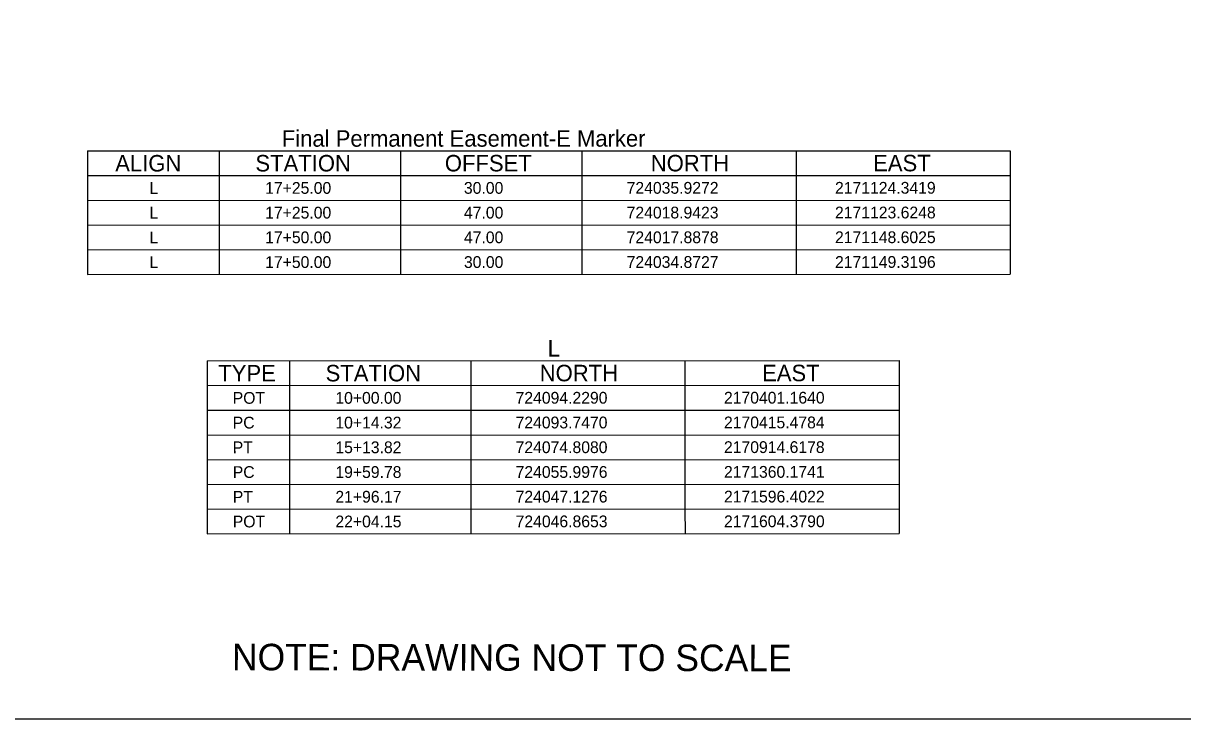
# Model space of a CAD drawing. Extents: x 2169223 to 2172151, y 723262 to 725175.
# Drawn here: x 2170358 to 2171309, y 723306 to 723876 of the extents above; entities that cross this region are included whole.
import ezdxf

# ---------------------------------------------------------------- set-up
doc = ezdxf.new("R2010")
doc.units = 0
for name, color, linetype in [('CTL Sheet Border CELL', 7, 'Continuous'), ('CTL Sheet Notes CELL', 7, 'Continuous'), ('CTL Sheet Table Cell', 7, 'Continuous'), ('CTL Sheet Text', 7, 'Continuous')]:
    doc.layers.add(name, color=color, linetype=linetype)

msp = doc.modelspace()

# ---------------------------------------------------------------- linework, layer by layer
at = {"layer": 'CTL Sheet Border CELL'}
msp.add_lwpolyline([(2172121.89, 725131.92), (2169513.19, 725131.84), (2169513.25, 723305.76), (2172121.95, 723305.85)], close=True, dxfattribs=at)
at = {"layer": 'CTL Sheet Table Cell'}
for p, q in [((2170410.96, 723771.1), (2171167.22, 723771.26)), ((2170410.96, 723771.1), (2170410.97, 723750.84)), ((2170519, 723771.12), (2170519, 723750.87)), ((2170667.55, 723771.16), (2170667.56, 723750.9)), ((2170816.1, 723771.19), (2170816.11, 723750.93)), ((2170991.66, 723771.23), (2170991.67, 723750.97)), ((2171167.22, 723771.26), (2171167.23, 723751.01)), ((2170410.97, 723750.84), (2171167.23, 723751.01)), ((2170410.97, 723750.84), (2170410.97, 723730.59)), ((2170519, 723750.87), (2170519.01, 723730.61)), ((2170667.56, 723750.9), (2170667.56, 723730.64)), ((2170816.11, 723750.93), (2170816.11, 723730.67)), ((2170991.67, 723750.97), (2170991.67, 723730.71)), ((2171167.23, 723751.01), (2171167.23, 723730.75)), ((2170410.97, 723730.59), (2171167.23, 723730.75)), ((2170410.97, 723730.59), (2170410.98, 723710.33)), ((2170519.01, 723730.61), (2170519.01, 723710.35)), ((2170667.56, 723730.64), (2170667.56, 723710.38)), ((2170816.11, 723730.67), (2170816.11, 723710.42)), ((2170991.67, 723730.71), (2170991.67, 723710.45)), ((2171167.23, 723730.75), (2171167.23, 723710.49)), ((2170410.98, 723710.33), (2171167.23, 723710.49)), ((2170410.98, 723710.33), (2170410.98, 723690.07)), ((2170519.01, 723710.35), (2170519.02, 723690.1)), ((2170667.56, 723710.38), (2170667.57, 723690.13)), ((2170816.11, 723710.42), (2170816.12, 723690.16)), ((2170991.67, 723710.45), (2170991.68, 723690.2)), ((2171167.23, 723710.49), (2171167.24, 723690.24)), ((2170410.98, 723690.07), (2171167.24, 723690.24)), ((2170410.98, 723690.07), (2170410.99, 723669.81)), ((2170519.02, 723690.1), (2170519.02, 723669.84)), ((2170667.57, 723690.13), (2170667.57, 723669.87)), ((2170816.12, 723690.16), (2170816.12, 723669.9)), ((2170991.68, 723690.2), (2170991.68, 723669.94)), ((2171167.24, 723690.24), (2171167.24, 723669.98)), ((2170410.99, 723669.81), (2171167.24, 723669.98)), ((2170509, 723599.07), (2171076.19, 723599.29)), ((2170509, 723599.07), (2170509.01, 723578.82)), ((2170576.52, 723599.1), (2170576.53, 723578.84)), ((2170725.07, 723599.16), (2170725.08, 723578.9)), ((2170900.63, 723599.23), (2170900.64, 723578.97)), ((2171076.19, 723599.29), (2171076.2, 723579.04)), ((2170509.01, 723578.82), (2171076.2, 723579.04)), ((2170509.01, 723578.82), (2170509.02, 723558.56)), ((2170576.53, 723578.84), (2170576.54, 723558.59)), ((2170725.08, 723578.9), (2170725.09, 723558.64)), ((2170900.64, 723578.97), (2170900.65, 723558.71)), ((2171076.2, 723579.04), (2171076.21, 723558.78)), ((2170509.02, 723558.56), (2171076.21, 723558.78)), ((2170509.02, 723558.56), (2170509.02, 723538.3)), ((2170576.54, 723558.59), (2170576.55, 723538.33)), ((2170725.09, 723558.64), (2170725.1, 723538.39)), ((2170900.65, 723558.71), (2170900.66, 723538.45)), ((2171076.21, 723558.78), (2171076.22, 723538.52)), ((2170509.02, 723538.3), (2171076.22, 723538.52)), ((2170509.02, 723538.3), (2170509.03, 723518.05)), ((2170576.55, 723538.33), (2170576.55, 723518.07)), ((2170725.1, 723538.39), (2170725.11, 723518.13)), ((2170900.66, 723538.45), (2170900.67, 723518.2)), ((2171076.22, 723538.52), (2171076.23, 723518.27)), ((2170509.03, 723518.05), (2171076.23, 723518.27)), ((2170509.03, 723518.05), (2170509.04, 723497.79)), ((2170576.55, 723518.07), (2170576.56, 723497.81)), ((2170725.11, 723518.13), (2170725.11, 723497.87)), ((2170900.67, 723518.2), (2170900.67, 723497.94)), ((2171076.23, 723518.27), (2171076.23, 723498.01)), ((2170509.04, 723497.79), (2171076.23, 723498.01)), ((2170576.56, 723497.81), (2170576.57, 723477.56)), ((2170725.11, 723497.87), (2170725.12, 723477.62)), ((2170900.67, 723497.94), (2170900.68, 723477.68)), ((2171076.23, 723498.01), (2171076.24, 723477.75)), ((2170509.04, 723497.79), (2170509.05, 723477.53)), ((2170509.05, 723477.53), (2171076.24, 723477.75)), ((2170509.05, 723477.53), (2170509.06, 723457.27)), ((2170576.57, 723477.56), (2170576.58, 723457.3)), ((2170725.12, 723477.62), (2170725.13, 723457.36)), ((2170900.68, 723477.68), (2170900.69, 723457.43)), ((2171076.24, 723477.75), (2171076.25, 723457.5)), ((2170509.06, 723457.27), (2171076.25, 723457.5))]:
    msp.add_line(p, q, dxfattribs=at)

# ---------------------------------------------------------------- texts
at = {"layer": 'CTL Sheet Border CELL'}
msp.add_text('NOTE: DRAWING NOT TO SCALE', height=21.7391, rotation=359.8966, dxfattribs=at).set_placement((2170529.39, 723345.53))
at = {"layer": 'CTL Sheet Notes CELL'}
for s, height, rotation, p in [('Final Permanent Easement-E Marker ', 13.5046, 0.01241, (2170570.25, 723774.51)), ('ALIGN', 13.505, 0.01241, (2170433.72, 723754.22)), ('STATION', 13.505, 0.01241, (2170548.62, 723754.25)), ('OFFSET', 13.505, 0.01241, (2170703.87, 723754.28)), ('NORTH', 13.505, 0.01241, (2170872.62, 723754.32)), ('EAST', 13.505, 0.01241, (2171054.88, 723754.36)), ('L', 13.5, 0.0223, (2170788.13, 723602.56)), ('TYPE', 13.505, 0.0223, (2170518.2, 723582.2)), ('STATION', 13.505, 0.0223, (2170606.14, 723582.23)), ('NORTH', 13.505, 0.0223, (2170781.6, 723582.3)), ('EAST', 13.505, 0.0223, (2170963.86, 723582.37))]:
    msp.add_text(s, height=height, rotation=rotation, dxfattribs=at).set_placement(p)
at = {"layer": 'CTL Sheet Text'}
for s, height, rotation, p in [('L', 9.65, 0.01241, (2170461.8, 723735.9)), ('17+25.00', 9.646, 0.01241, (2170556.6, 723735.92)), ('30.00', 9.646, 0.01241, (2170719.5, 723735.96)), ('724035.9272', 9.6461, 0.01241, (2170852.85, 723735.99)), ('2171124.3419', 9.6461, 0.01241, (2171023.62, 723736.02)), ('L', 9.65, 0.01241, (2170461.8, 723715.65)), ('17+25.00', 9.646, 0.01241, (2170556.6, 723715.67)), ('47.00', 9.646, 0.01241, (2170719.51, 723715.7)), ('724018.9423', 9.6461, 0.01241, (2170852.85, 723715.73)), ('2171123.6248', 9.6461, 0.01241, (2171023.63, 723715.77)), ('L', 9.65, 0.01241, (2170461.81, 723695.39)), ('17+50.00', 9.646, 0.01241, (2170556.61, 723695.41)), ('47.00', 9.646, 0.01241, (2170719.51, 723695.44)), ('724017.8878', 9.6461, 0.01241, (2170852.86, 723695.47)), ('2171148.6025', 9.6461, 0.01241, (2171023.63, 723695.51)), ('L', 9.65, 0.01241, (2170461.81, 723675.13)), ('17+50.00', 9.646, 0.01241, (2170556.61, 723675.15)), ('30.00', 9.646, 0.01241, (2170719.52, 723675.19)), ('724034.8727', 9.6461, 0.01241, (2170852.86, 723675.22)), ('2171149.3196', 9.6461, 0.01241, (2171023.64, 723675.25)), ('2170401.1640', 9.6461, 0.0223, (2170932.6, 723564.03)), ('POT', 9.646, 0.0223, (2170530.01, 723563.87)), ('10+00.00', 9.646, 0.0223, (2170614.13, 723563.91)), ('724094.2290', 9.6461, 0.0223, (2170761.83, 723563.96)), ('PC ', 9.646, 0.0223, (2170530.02, 723543.62)), ('10+14.32', 9.646, 0.0223, (2170614.13, 723543.65)), ('724093.7470', 9.6461, 0.0223, (2170761.83, 723543.71)), ('2170415.4784', 9.6461, 0.0223, (2170932.61, 723543.77)), ('PT ', 9.646, 0.0223, (2170530.03, 723523.36)), ('15+13.82', 9.646, 0.0223, (2170614.14, 723523.39)), ('724074.8080', 9.6461, 0.0223, (2170761.84, 723523.45)), ('2170914.6178', 9.6461, 0.0223, (2170932.62, 723523.52)), ('PC ', 9.646, 0.0223, (2170530.04, 723503.1)), ('19+59.78', 9.646, 0.0223, (2170614.15, 723503.13)), ('724055.9976', 9.6461, 0.0223, (2170761.85, 723503.19)), ('2171360.1741', 9.6461, 0.0223, (2170932.62, 723503.26)), ('PT ', 9.646, 0.0223, (2170530.05, 723482.84)), ('21+96.17', 9.646, 0.0223, (2170614.16, 723482.88)), ('724047.1276', 9.6461, 0.0223, (2170761.86, 723482.94)), ('2171596.4022', 9.6461, 0.0223, (2170932.63, 723483)), ('POT', 9.646, 0.0223, (2170530.05, 723462.59)), ('22+04.15', 9.646, 0.0223, (2170614.17, 723462.62)), ('724046.8653', 9.6461, 0.0223, (2170761.87, 723462.68)), ('2171604.3790', 9.6461, 0.0223, (2170932.64, 723462.74))]:
    msp.add_text(s, height=height, rotation=rotation, dxfattribs=at).set_placement(p)

doc.saveas('drawing.dxf')
